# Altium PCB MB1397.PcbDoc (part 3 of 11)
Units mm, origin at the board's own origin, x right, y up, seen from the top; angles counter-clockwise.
Board outline 118.24 x 172.86 mm, 6 copper layers (Top Layer, L2_GND, L3_VCC, L4_SIG, L5_GND, Bottom Layer), stack 1.631 mm thick; 819 components, 632 nets, 2875 pads, 1523 vias.
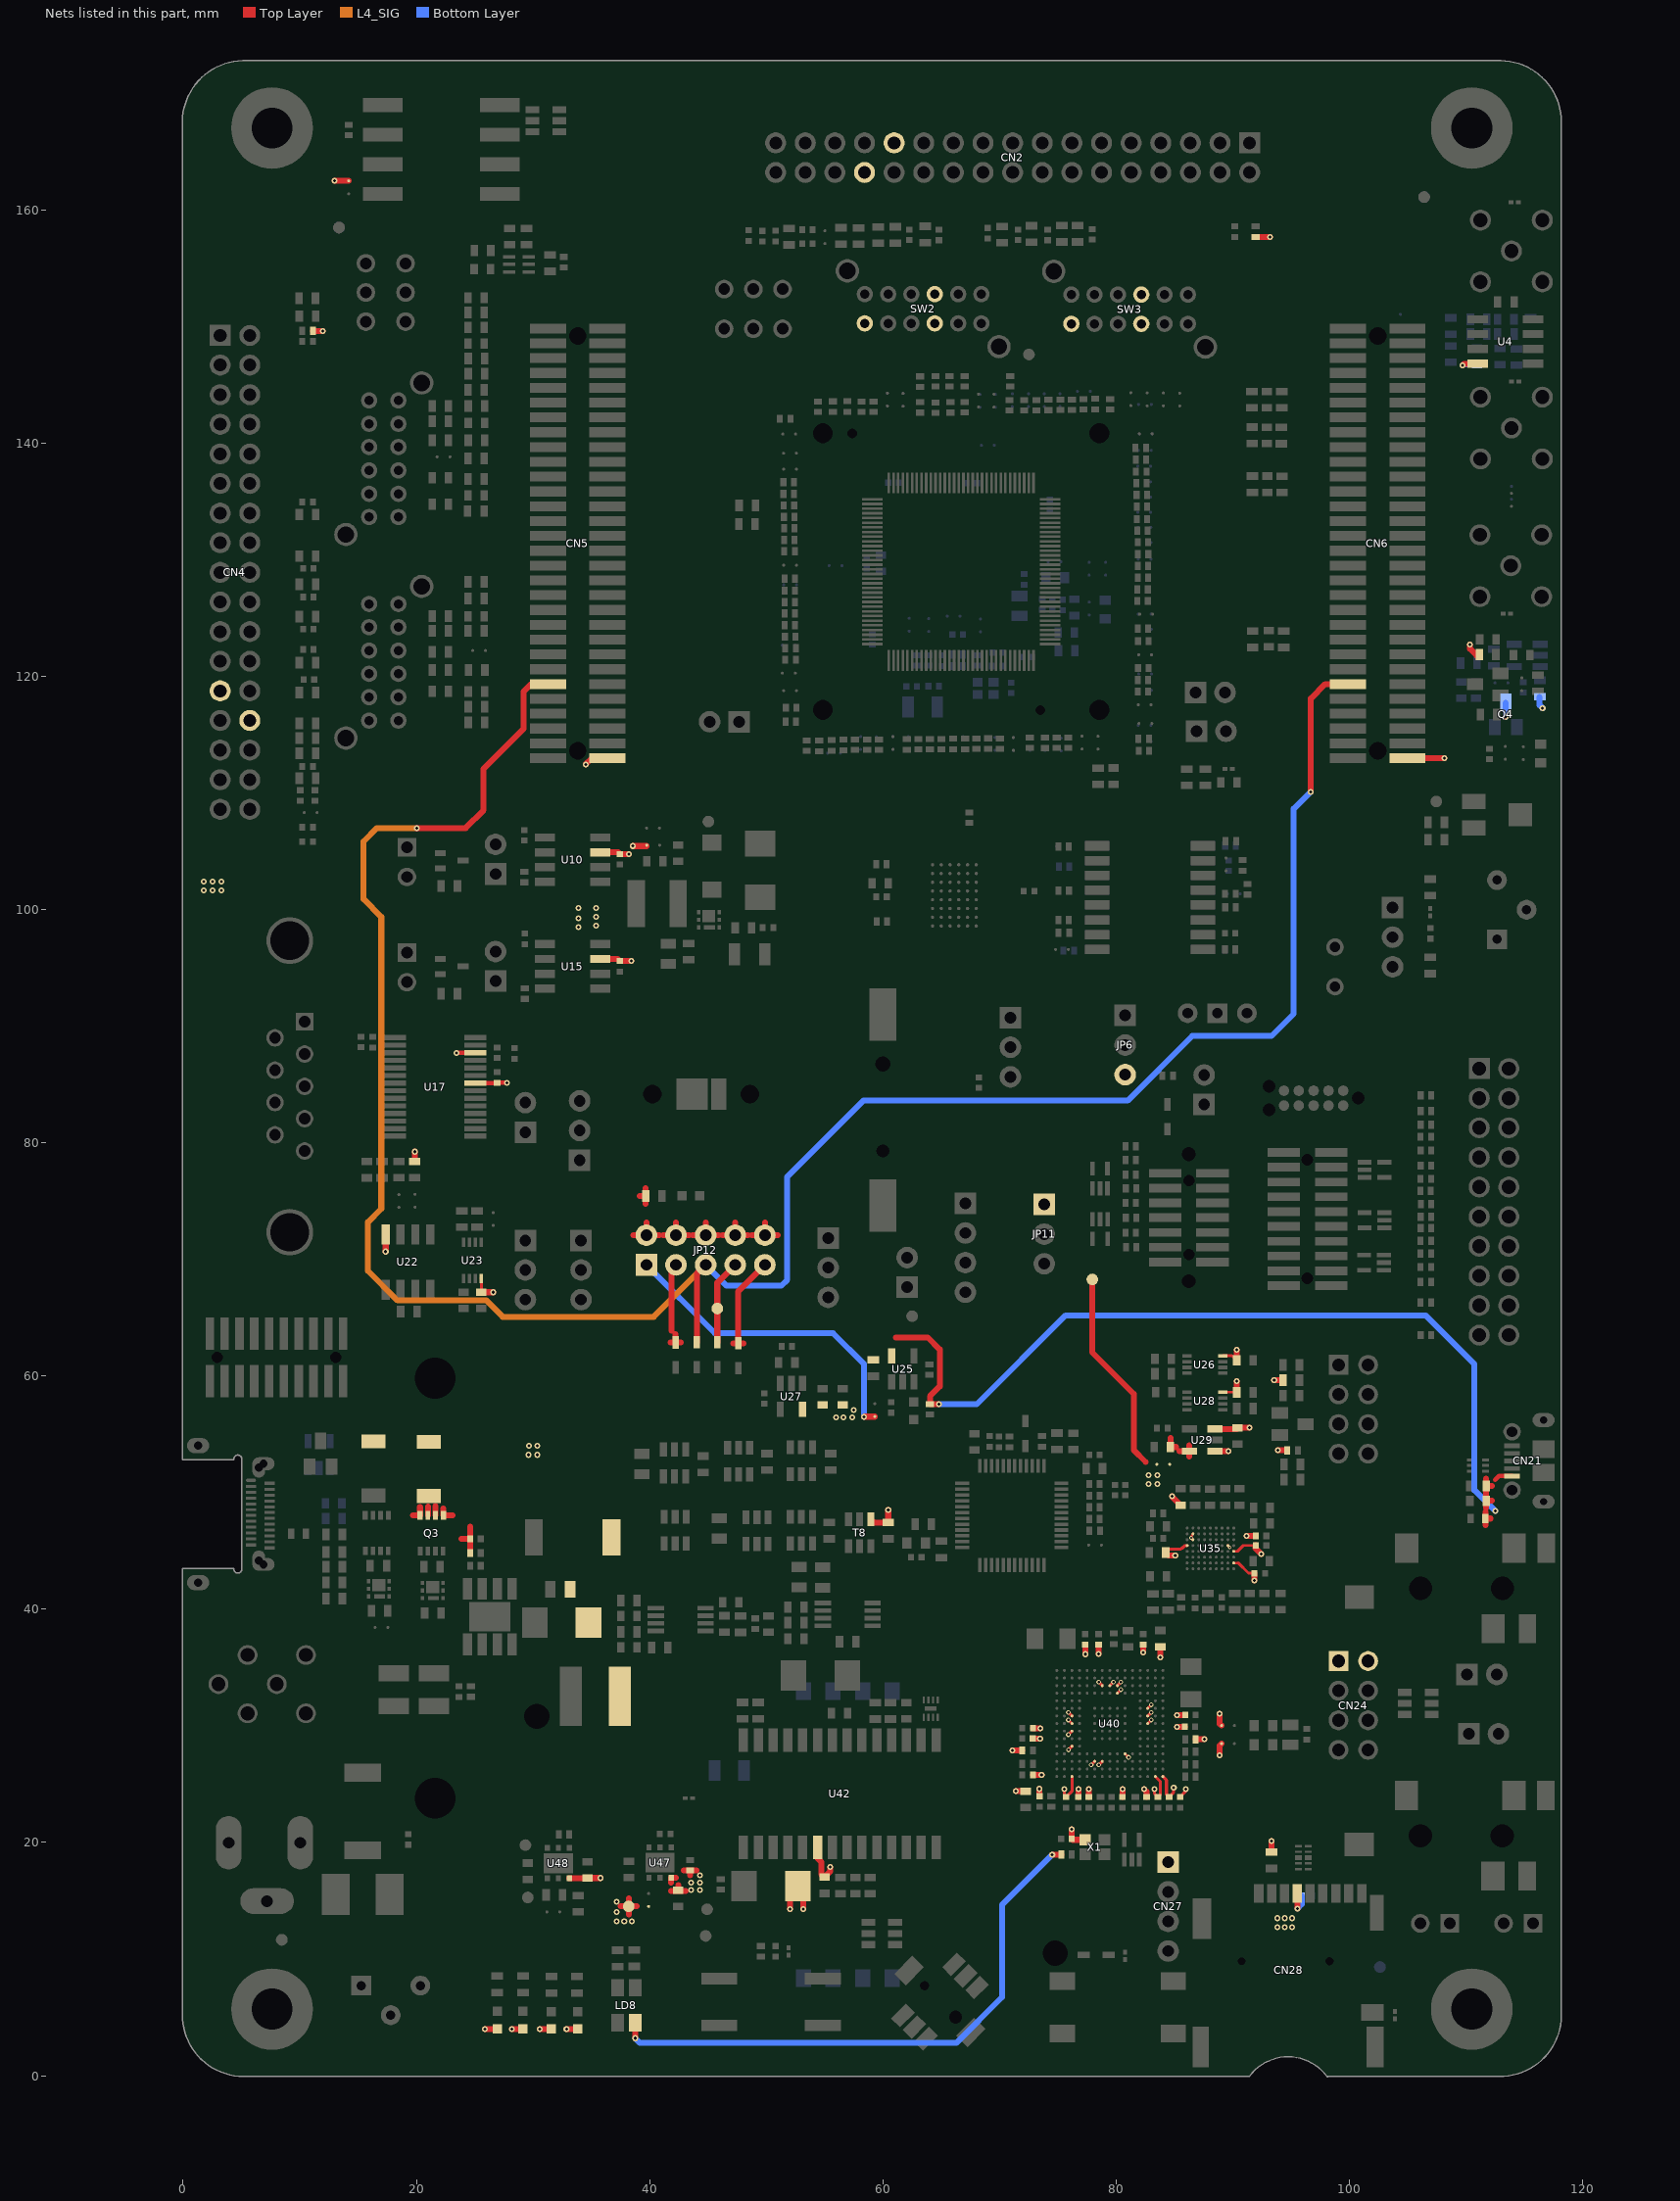
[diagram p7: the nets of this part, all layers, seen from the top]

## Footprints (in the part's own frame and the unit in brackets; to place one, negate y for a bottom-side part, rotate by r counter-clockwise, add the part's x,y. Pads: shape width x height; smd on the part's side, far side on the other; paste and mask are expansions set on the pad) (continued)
ICC_LQFP128_14X14_P040_SOCKET_IRONWOOD_SG-QFE-7011MF [mm]
  rect 1.78x0.225 smd mask+0.038: 1(-7.62,6.2) 2(-7.62,5.8) 3(-7.62,5.4) 4(-7.62,5) 5(-7.62,4.6) 6(-7.62,4.2) 7(-7.62,3.8) 8(-7.62,3.4) 9(-7.62,3) 10(-7.62,2.6) 11(-7.62,2.2) 12(-7.62,1.8) 13(-7.62,1.4) 14(-7.62,1) 15(-7.62,0.6) 16(-7.62,0.2) 17(-7.62,-0.2) 18(-7.62,-0.6) 19(-7.62,-1) 20(-7.62,-1.4) 21(-7.62,-1.8) 22(-7.62,-2.2) 23(-7.62,-2.6) 24(-7.62,-3) 25(-7.62,-3.4) 26(-7.62,-3.8) 27(-7.62,-4.2) 28(-7.62,-4.6) 29(-7.62,-5) 30(-7.62,-5.4) 31(-7.62,-5.8) 32(-7.62,-6.2) 65(7.62,-6.2) 66(7.62,-5.8) 67(7.62,-5.4) 68(7.62,-5) 69(7.62,-4.6) 70(7.62,-4.2) 71(7.62,-3.8) 72(7.62,-3.4) 73(7.62,-3) 74(7.62,-2.6) 75(7.62,-2.2) 76(7.62,-1.8) 77(7.62,-1.4) 78(7.62,-1) 79(7.62,-0.6) 80(7.62,-0.2) 81(7.62,0.2) 82(7.62,0.6) 83(7.62,1) 84(7.62,1.4) 85(7.62,1.8) 86(7.62,2.2) 87(7.62,2.6) 88(7.62,3) 89(7.62,3.4) 90(7.62,3.8) 91(7.62,4.2) 92(7.62,4.6) 93(7.62,5) 94(7.62,5.4) 95(7.62,5.8) 96(7.62,6.2)
  rect 0.225x1.78 smd mask+0.038: 33(-6.2,-7.62) 34(-5.8,-7.62) 35(-5.4,-7.62) 36(-5,-7.62) 37(-4.6,-7.62) 38(-4.2,-7.62) 39(-3.8,-7.62) 40(-3.4,-7.62) 41(-3,-7.62) 42(-2.6,-7.62) 43(-2.2,-7.62) 44(-1.8,-7.62) 45(-1.4,-7.62) 46(-1,-7.62) 47(-0.6,-7.62) 48(-0.2,-7.62) 49(0.2,-7.62) 50(0.6,-7.62) 51(1,-7.62) 52(1.4,-7.62) 53(1.8,-7.62) 54(2.2,-7.62) 55(2.6,-7.62) 56(3,-7.62) 57(3.4,-7.62) 58(3.8,-7.62) 59(4.2,-7.62) 60(4.6,-7.62) 61(5,-7.62) 62(5.4,-7.62) 63(5.8,-7.62) 64(6.2,-7.62) 97(6.2,7.62) 98(5.8,7.62) 99(5.4,7.62) 100(5,7.62) 101(4.6,7.62) 102(4.2,7.62) 103(3.8,7.62) 104(3.4,7.62) 105(3,7.62) 106(2.6,7.62) 107(2.2,7.62) 108(1.8,7.62) 109(1.4,7.62) 110(1,7.62) 111(0.6,7.62) 112(0.2,7.62) 113(-0.2,7.62) 114(-0.6,7.62) 115(-1,7.62) 116(-1.4,7.62) 117(-1.8,7.62) 118(-2.2,7.62) 119(-2.6,7.62) 120(-3,7.62) 121(-3.4,7.62) 122(-3.8,7.62) 123(-4.2,7.62) 124(-4.6,7.62) 125(-5,7.62) 126(-5.4,7.62) 127(-5.8,7.62) 128(-6.2,7.62)
  round 0 hole 1.71 unplated mask+0.05: NPTH1(-11.86,11.86) NPTH2(11.86,11.86) NPTH3(11.86,-11.86) NPTH4(-11.86,-11.86)
  round 0 hole 0.85 unplated mask+0.05: NPTH5(-11.86,-6.78) NPTH6(11.86,9.32)
  Bottom Layer keep-out circle w0.01: c-11.86,11.86 r2.5
  Bottom Layer keep-out circle w0.01: c11.865,11.86 r2.5
  Bottom Layer keep-out circle w0.01: c11.86,-11.86 r2.5
  Bottom Layer keep-out circle w0.01: c-11.86,-11.86 r2.5
  Keep-Out Layer circle w0.01: c11.86,9.32 r0.7
  Keep-Out Layer circle w0.01: c-11.86,11.86 r1.1
  Keep-Out Layer circle w0.01: c11.86,11.86 r1.1
  Keep-Out Layer circle w0.01: c11.86,-11.86 r1.1
  Keep-Out Layer circle w0.01: c-11.86,-11.86 r1.1
  Keep-Out Layer circle w0.01: c-11.86,-6.78 r0.7
  silkscreen extent -13.18,-13.18 13.18,13.18, body extent -14.36,-14.36 14.36,14.36, height 9.86
ICC_MINI-BGA48_9X11_P075 [mm] "IPC"
  round 0.28 smd mask+0.05: A1(-1.875,2.625) A2(-1.125,2.625) A3(-0.375,2.625) A4(0.375,2.625) A5(1.125,2.625) A6(1.875,2.625) B1(-1.875,1.875) B2(-1.125,1.875) B3(-0.375,1.875) B4(0.375,1.875) B5(1.125,1.875) B6(1.875,1.875) C1(-1.875,1.125) C2(-1.125,1.125) C3(-0.375,1.125) C4(0.375,1.125) C5(1.125,1.125) C6(1.875,1.125) D1(-1.875,0.375) D2(-1.125,0.375) D3(-0.375,0.375) D4(0.375,0.375) D5(1.125,0.375) D6(1.875,0.375) E1(-1.875,-0.375) E2(-1.125,-0.375) E3(-0.375,-0.375) E4(0.375,-0.375) E5(1.125,-0.375) E6(1.875,-0.375) F1(-1.875,-1.125) F2(-1.125,-1.125) F3(-0.375,-1.125) F4(0.375,-1.125) F5(1.125,-1.125) F6(1.875,-1.125) G1(-1.875,-1.875) G2(-1.125,-1.875) G3(-0.375,-1.875) G4(0.375,-1.875) G5(1.125,-1.875) G6(1.875,-1.875) H1(-1.875,-2.625) H2(-1.125,-2.625) H3(-0.375,-2.625) H4(0.375,-2.625) H5(1.125,-2.625) H6(1.875,-2.625)
  silkscreen extent -4.7,-5.55 4.55,5.7, body extent -4.55,-5.55 4.55,5.55, height 1.21
ICC_MINISO8_3X3_P065 [mm]
  rect 0.4x1.4 smd mask+0.05: 1(0.975,2.125) 2(0.325,2.125) 3(-0.325,2.125) 4(-0.975,2.125) 5(-0.975,-2.125) 6(-0.325,-2.125) 7(0.325,-2.125) 8(0.975,-2.125)
  silkscreen extent -1.6,-1.55 1.6,1.55, body extent -1.6,-2.58 1.6,2.58, height 1.11
ICC_SO8_5X4_P127 [mm]
  rect 0.7x1.75 smd mask+0.05: 1(-1.905,-2.375) 2(-0.635,-2.375) 3(0.635,-2.375) 4(1.905,-2.375) 5(1.905,2.375) 6(0.635,2.375) 7(-0.635,2.375) 8(-1.905,2.375)
  silkscreen extent -2.58,-2 2.58,2, body extent -2.57,-3 2.57,3, height 1.75
ICC_SO28_18P10X7P60_P127 [mm]
  rect 0.8x2.02 smd mask+0.05: 1(-8.255,-4.59) 2(-6.985,-4.59) 3(-5.715,-4.59) 4(-4.445,-4.59) 5(-3.175,-4.59) 6(-1.905,-4.59) 7(-0.635,-4.59) 8(0.635,-4.59) 9(1.905,-4.59) 10(3.175,-4.59) 11(4.445,-4.59) 12(5.715,-4.59) 13(6.985,-4.59) 14(8.255,-4.59) 15(8.255,4.59) 16(6.985,4.59) 17(5.715,4.59) 18(4.445,4.59) 19(3.175,4.59) 20(1.905,4.59) 21(0.635,4.59) 22(-0.635,4.59) 23(-1.905,4.59) 24(-3.175,4.59) 25(-4.445,4.59) 26(-5.715,4.59) 27(-6.985,4.59) 28(-8.255,4.59)
  silkscreen extent -9.05,-3.8 9.05,3.8, body extent -9.05,-5.16 9.05,5.16, height 2.65
ICC_SOP2-SF_16P_10P3X7P5_P127 [mm]
  rect 0.8x2.1 smd mask+0.05: 1(-4.445,-4.55) 2(-3.175,-4.55) 3(-1.905,-4.55) 4(-0.635,-4.55) 5(0.635,-4.55) 6(1.905,-4.55) 7(3.175,-4.55) 8(4.445,-4.55) 9(4.445,4.55) 10(3.175,4.55) 11(1.905,4.55) 12(0.635,4.55) 13(-0.635,4.55) 14(-1.905,4.55) 15(-3.175,4.55) 16(-4.445,4.55)
  silkscreen extent -5.25,-3.8 5.25,3.8, body extent -5.25,-5.35 5.25,5.35, height 2.66
ICC_SOT23-3L_H1P12 [mm]
  rect 1x1.4 smd mask+0.05: 1(-0.95,-1.1) 2(0.95,-1.1) 3(0,1.1)
  silkscreen extent -1.63,-0.82 1.63,0.82, body extent -1.56,-1.25 1.56,1.25, height 1.12
ICC_SOT23-5L_H1P45 [mm]
  rect 0.6x1.3 smd mask+0.05: 1(-0.95,-1.1) 2(0,-1.1) 3(0.95,-1.1) 4(0.95,1.1) 5(-0.95,1.1)
  silkscreen extent -1.75,-1.68 1.6,0.97, body extent -1.52,-1.25 1.52,1.25, height 1.45
ICC_SSOP28_10P2X5P3_P065 [mm]
  rect 0.45x1.9 smd mask+0.05: 1(-4.225,-3.45) 2(-3.575,-3.45) 3(-2.925,-3.45) 4(-2.275,-3.45) 5(-1.625,-3.45) 6(-0.975,-3.45) 7(-0.325,-3.45) 8(0.325,-3.45) 9(0.975,-3.45) 10(1.625,-3.45) 11(2.275,-3.45) 12(2.925,-3.45) 13(3.575,-3.45) 14(4.225,-3.45) 15(4.225,3.45) 16(3.575,3.45) 17(2.925,3.45) 18(2.275,3.45) 19(1.625,3.45) 20(0.975,3.45) 21(0.325,3.45) 22(-0.325,3.45) 23(-0.975,3.45) 24(-1.625,3.45) 25(-2.275,3.45) 26(-2.925,3.45) 27(-3.575,3.45) 28(-4.225,3.45)
  silkscreen extent -5.25,-2.8 5.25,2.8, body extent -5.25,-3.9 5.25,3.9, height 2
ICC_UDFN6_2X2_P065 [mm] "MCD-01551"
  rect 0.3x1.05 smd mask+0.05: 1(-0.65,-0.85) 2(0,-0.85) 3(0.65,-0.85) 4(0.65,0.85) 5(0,0.85) 6(-0.65,0.85)
  silkscreen extent -1.15,-1.45 1.02,1.02, body extent -1.03,-1.03 1.02,1.02, height 0.56
ICC_UFBGA201_176+25_10X10_P065 [mm] "IPC"
  round 0.25 smd mask+0.05: A1(-4.55,4.55) A2(-3.9,4.55) A3(-3.25,4.55) A4(-2.6,4.55) A5(-1.95,4.55) A6(-1.3,4.55) A7(-0.65,4.55) A8(0,4.55) A9(0.65,4.55) A10(1.3,4.55) A11(1.95,4.55) A12(2.6,4.55) A13(3.25,4.55) A14(3.9,4.55) A15(4.55,4.55) B1(-4.55,3.9) B2(-3.9,3.9) B3(-3.25,3.9) B4(-2.6,3.9) B5(-1.95,3.9) B6(-1.3,3.9) B7(-0.65,3.9) B8(0,3.9) B9(0.65,3.9) B10(1.3,3.9) B11(1.95,3.9) B12(2.6,3.9) B13(3.25,3.9) B14(3.9,3.9) B15(4.55,3.9) C1(-4.55,3.25) C2(-3.9,3.25) C3(-3.25,3.25) C4(-2.6,3.25) C5(-1.95,3.25) C6(-1.3,3.25) C7(-0.65,3.25) C8(0,3.25) C9(0.65,3.25) C10(1.3,3.25) C11(1.95,3.25) C12(2.6,3.25) C13(3.25,3.25) C14(3.9,3.25) C15(4.55,3.25) D1(-4.55,2.6) D2(-3.9,2.6) D3(-3.25,2.6) D4(-2.6,2.6) D5(-1.95,2.6) D6(-1.3,2.6) D7(-0.65,2.6) D8(0,2.6) D9(0.65,2.6) D10(1.3,2.6) D11(1.95,2.6) D12(2.6,2.6) D13(3.25,2.6) D14(3.9,2.6) D15(4.55,2.6) E1(-4.55,1.95) E2(-3.9,1.95) E3(-3.25,1.95) E4(-2.6,1.95) E12(2.6,1.95) E13(3.25,1.95) E14(3.9,1.95) E15(4.55,1.95) F1(-4.55,1.3) F2(-3.9,1.3) F3(-3.25,1.3) F4(-2.6,1.3) F6(-1.3,1.3) F7(-0.65,1.3) F8(0,1.3) F9(0.65,1.3) F10(1.3,1.3) F12(2.6,1.3) F13(3.25,1.3) F14(3.9,1.3) F15(4.55,1.3) G1(-4.55,0.65) G2(-3.9,0.65) G3(-3.25,0.65) G4(-2.6,0.65) G6(-1.3,0.65) G7(-0.65,0.65) G8(0,0.65) G9(0.65,0.65) G10(1.3,0.65) G12(2.6,0.65) G13(3.25,0.65) G14(3.9,0.65) G15(4.55,0.65) H1(-4.55,0) H2(-3.9,0) H3(-3.25,0) H4(-2.6,0) H6(-1.3,0) H7(-0.65,0) H8(0,0) H9(0.65,0) H10(1.3,0) H12(2.6,0) H13(3.25,0) H14(3.9,0) H15(4.55,0) J1(-4.55,-0.65) J2(-3.9,-0.65) J3(-3.25,-0.65) J4(-2.6,-0.65) J6(-1.3,-0.65) J7(-0.65,-0.65) J8(0,-0.65) J9(0.65,-0.65) J10(1.3,-0.65) J12(2.6,-0.65) J13(3.25,-0.65) J14(3.9,-0.65) J15(4.55,-0.65) K1(-4.55,-1.3) K2(-3.9,-1.3) K3(-3.25,-1.3) K4(-2.6,-1.3) K6(-1.3,-1.3) K7(-0.65,-1.3) K8(0,-1.3) K9(0.65,-1.3) K10(1.3,-1.3) K12(2.6,-1.3) K13(3.25,-1.3) K14(3.9,-1.3) K15(4.55,-1.3) L1(-4.55,-1.95) L2(-3.9,-1.95) L3(-3.25,-1.95) L4(-2.6,-1.95) L12(2.6,-1.95) L13(3.25,-1.95) L14(3.9,-1.95) L15(4.55,-1.95) M1(-4.55,-2.6) M2(-3.9,-2.6) M3(-3.25,-2.6) M4(-2.6,-2.6) M5(-1.95,-2.6) M6(-1.3,-2.6) M7(-0.65,-2.6) M8(0,-2.6) M9(0.65,-2.6) M10(1.3,-2.6) M11(1.95,-2.6) M12(2.6,-2.6) M13(3.25,-2.6) M14(3.9,-2.6) M15(4.55,-2.6) N1(-4.55,-3.25) N2(-3.9,-3.25) N3(-3.25,-3.25) N4(-2.6,-3.25) N5(-1.95,-3.25) N6(-1.3,-3.25) N7(-0.65,-3.25) N8(0,-3.25) N9(0.65,-3.25) N10(1.3,-3.25) N11(1.95,-3.25) N12(2.6,-3.25) N13(3.25,-3.25) N14(3.9,-3.25) N15(4.55,-3.25) P1(-4.55,-3.9) P2(-3.9,-3.9) P3(-3.25,-3.9) P4(-2.6,-3.9) P5(-1.95,-3.9) P6(-1.3,-3.9) P7(-0.65,-3.9) P8(0,-3.9) P9(0.65,-3.9) P10(1.3,-3.9) P11(1.95,-3.9) P12(2.6,-3.9) P13(3.25,-3.9) P14(3.9,-3.9) P15(4.55,-3.9) R1(-4.55,-4.55) R2(-3.9,-4.55) R3(-3.25,-4.55) R4(-2.6,-4.55) R5(-1.95,-4.55) R6(-1.3,-4.55) R7(-0.65,-4.55) R8(0,-4.55) R9(0.65,-4.55) R10(1.3,-4.55) R11(1.95,-4.55) R12(2.6,-4.55) R13(3.25,-4.55) R14(3.9,-4.55) R15(4.55,-4.55)
  silkscreen extent -5.22,-5.07 5.07,5.23, body extent -5.07,-5.07 5.07,5.07, height 0.61
ICC_VSSOP8_DCU_R-PDSO-G8_2X2P30_P050 [mm]
  rect 0.3x0.8 smd mask+0.05: 1(-0.75,-1.55) 2(-0.25,-1.55) 3(0.25,-1.55) 4(0.75,-1.55) 5(0.75,1.55) 6(0.25,1.55) 7(-0.25,1.55) 8(-0.75,1.55)
  silkscreen extent -1.05,-1.2 1.05,1.2, body extent -1.05,-1.62 1.05,1.62, height 0.9
ICC_W-CSP-BGA72_4P511X4P023_P050 [mm]
  round 0.25 smd mask+0.05: A1(-2,1.75) A2(-1.5,1.75) A3(-1,1.75) A4(-0.5,1.75) A5(0,1.75) A6(0.5,1.75) A7(1,1.75) A8(1.5,1.75) A9(2,1.75) B1(-2,1.25) B2(-1.5,1.25) B3(-1,1.25) B4(-0.5,1.25) B5(0,1.25) B6(0.5,1.25) B7(1,1.25) B8(1.5,1.25) B9(2,1.25) C1(-2,0.75) C2(-1.5,0.75) C3(-1,0.75) C4(-0.5,0.75) C5(0,0.75) C6(0.5,0.75) C7(1,0.75) C8(1.5,0.75) C9(2,0.75) D1(-2,0.25) D2(-1.5,0.25) D3(-1,0.25) D4(-0.5,0.25) D5(0,0.25) D6(0.5,0.25) D7(1,0.25) D8(1.5,0.25) D9(2,0.25) E1(-2,-0.25) E2(-1.5,-0.25) E3(-1,-0.25) E4(-0.5,-0.25) E5(0,-0.25) E6(0.5,-0.25) E7(1,-0.25) E8(1.5,-0.25) E9(2,-0.25) F1(-2,-0.75) F2(-1.5,-0.75) F3(-1,-0.75) F4(-0.5,-0.75) F5(0,-0.75) F6(0.5,-0.75) F7(1,-0.75) F8(1.5,-0.75) F9(2,-0.75) G1(-2,-1.25) G2(-1.5,-1.25) G3(-1,-1.25) G4(-0.5,-1.25) G5(0,-1.25) G6(0.5,-1.25) G7(1,-1.25) G8(1.5,-1.25) G9(2,-1.25) H1(-2,-1.75) H2(-1.5,-1.75) H3(-1,-1.75) H4(-0.5,-1.75) H5(0,-1.75) H6(0.5,-1.75) H7(1,-1.75) H8(1.5,-1.75) H9(2,-1.75)
  silkscreen extent -2.42,-2.03 2.28,2.17, body extent -2.28,-2.04 2.28,2.04, height 0.78
IND_POWER_CYNTEC_PSI054T [mm]
  rect 1.5x4 smd mask+0.05: 1(-1.8,0) 2(1.8,0)
  silkscreen extent -2.55,-2.55 2.55,2.55, body extent -2.55,-2.55 2.55,2.55, height 4
IND_TDK_VLS6045EX-4R7M [mm]
  rect 1.9x5.1 smd mask+0.05: 1(-2.1,0) 2(2.1,0)
  silkscreen extent -2.75,-3 2.75,3, body extent -3,-3 3,3, height 4.51
L0603 [mm]
  rect 0.8x0.95 smd mask+0.05: 1(-0.8,0) 2(0.8,0)
  silkscreen extent -1.33,-0.6 1.33,0.6, body extent -0.87,-0.47 0.87,0.47, height 0.95
LED_0603_OSRAM_LB-Q39G-L2OO-35-1_BLUE_1A2K_H0P4 [mm]
  rect 0.8x0.8 smd mask+0.05: 1(-0.75,0) 2(0.75,0)
  silkscreen extent -0.85,-0.53 1.28,0.53, body extent -0.85,-0.45 0.85,0.45, height 0.6
LED_0603_OSRAM_LG-Q396-PS-35_GREEN_1A2K_H0P4 [mm]
  rect 0.8x0.8 smd mask+0.05: 1(-0.75,0) 2(0.75,0)
  silkscreen extent -0.85,-0.53 1.28,0.53, body extent -0.85,-0.45 0.85,0.45, height 0.6
LED_0603_OSRAM_LO-Q976-PS-25_ORANGE_1A2K_H0P8 [mm]
  rect 0.8x0.8 smd mask+0.05: 1(-0.75,0) 2(0.75,0)
  silkscreen extent -0.85,-0.53 1.28,0.53, body extent -0.85,-0.45 0.85,0.45, height 0.8
LED_0603_VISHAY_VLMS1300-GS08_RED_1A2K_H0P8 [mm]
  rect 0.8x0.8 smd mask+0.05: 1(-0.75,0) 2(0.75,0)
  silkscreen extent -0.85,-0.53 1.28,0.53, body extent -0.85,-0.45 0.85,0.45, height 0.8
LED_BI-GR_HSMF-A201-A00J1 [mm]
  rect 1.1x1.5 smd mask+0.05: 1(-0.75,-1.5) 2(-0.75,1.5) 3(0.75,1.5) 4(0.75,-1.5)
  silkscreen extent -1.65,-1.85 1.65,1.85, body extent -1.5,-1.85 1.5,1.85, height 2.1
LED_EVERLUCK_CWC12100_WHITE_1A2K [mm] "BOTTOM PLACE"
  rect 1.3x2.7 smd mask+0.05: 1(1.5,0)
  rect 2.7x2.7 smd mask+0.05: 2(-0.8,0)
  silkscreen extent -2.22,-1.63 1.65,1.62, body extent -1.75,-1.5 1.75,1.5, height 2.5
LIGHT_10MM-SQUARE-LIGHT-BAR_LUMEX_LPB-S01110101S-110945 [mm]
  round 0 hole 1.6 slot 3.8 at 90 deg unplated mask+0.05: NPTH1(-4.18,0) NPTH2(4.18,0)
  silkscreen extent -5.08,-5.08 5.08,5.08, body extent -5.08,-5.08 5.08,5.08, height 10.3
LOGO_CE [mm]
  silkscreen extent -1.61,-1.37 1.85,1.07
LOGO_MAIN_1 [mm]
  silkscreen extent -3.36,-2.51 3.52,3.76
LOGO_ROHS [mm]
  silkscreen extent -4.63,-3.03 4.87,2.98
LOGO_ST [mm]
  silkscreen extent -6.18,-2.95 5.25,3.14
MOS_POWERFLAT_2X2_P065 [mm] "MCD-01028  PowerFLAT, 6-Leads, Body 2.1x2.1mm"
  rect 0.35x0.3 smd mask+0.038: 1(-0.65,-0.875) 2(0,-0.875)
  rect 0.35x0.3 smd mask+0.05: 3(0.65,-0.875) 4(0.65,0.875) 5(0,0.875) 6(-0.65,0.875)
  rect 0.35x0.95 smd mask+0.05: 7(0.65,0.05)
  rect 1.05x1.125 smd mask+0.038: 8(-0.3,-0.012)
  silkscreen extent -1.2,-1.2 1.05,1.05, body extent -1.05,-1.05 1.05,1.05, height 0.81
MOS_POWERFLAT_3P3X3P3_P065 [mm]
  rect 0.4x0.75 smd mask+0.05: 1(-0.975,-1.525) 2(-0.325,-1.525) 3(0.325,-1.525) 4(0.975,-1.525) 6(0.325,1.525) 7(-0.325,1.525)
  rect 0.45x0.75 smd mask+0.05: 5(1,1.525) 8(-1,1.525)
  Top Layer region: -1.755,0.2 -1.755,-0.2 -1.225,-0.2 -1.225,-0.5 1.225,-0.5 1.225,-0.2 1.755,-0.2 1.755,0.2 1.225,0.2 1.225,1.9 -1.225,1.9 -1.225,0.2
  silkscreen extent -1.63,-1.55 1.63,1.55, body extent -1.75,-1.75 1.75,1.75, height 0.91
MOS_SOT23 [mm]
  rect 1x1.4 smd mask+0.05: 1(-0.95,-1.1) 2(0.95,-1.1) 3(0,1.1)
  silkscreen extent -1.63,-0.82 1.63,0.82, body extent -1.56,-1.25 1.56,1.25, height 1.1
MOS_SOT23-5L [mm]
  rect 0.6x1.3 smd mask+0.05: 1(-0.95,-1.1) 2(0,-1.1) 3(0.95,-1.1) 4(0.95,1.1) 5(-0.95,1.1)
  silkscreen extent -1.6,-0.95 1.6,0.97, body extent -1.52,-1.25 1.52,1.25, height 1.45
MOS_SOT23-6L [mm]
  rect 0.6x1.2 smd mask+0.05: 1(-0.95,-1.15) 2(0,-1.15) 3(0.95,-1.15) 4(0.95,1.15) 5(0,1.15) 6(-0.95,1.15)
  silkscreen extent -1.53,-0.87 1.53,0.87, body extent -1.52,-1.5 1.52,1.5, height 1.3
NPN_SOT23 [mm]
  rect 1x1.4 smd mask+0.05: 1(-0.95,-1.1) 2(0.95,-1.1) 3(0,1.1)
  silkscreen extent -1.63,-0.82 1.63,0.82, body extent -1.56,-1.25 1.56,1.25, height 1.1
NPTH_350 [mm]
  round 0 hole 3.5 unplated mask+0.05: 1(0,0)
  silkscreen extent -2,-2 2,2
OSC_NDK_NZ2520SB_4P [mm]
  rect 1x1 smd mask+0.05: 1(-0.825,-0.625) 2(0.825,-0.625) 3(0.825,0.625) 4(-0.825,0.625)
  silkscreen extent -1.43,-1.22 1.2,1.05, body extent -1,-0.77 -0.6,-0.38, height 0.91
PHO_SENBAN_GL55XX [mm]
  round 1.5 hole 0.9 mask+0.05: 1(-1.7,0) 2(1.7,0)
  silkscreen extent -2.6,-2.25 2.6,2.25, body extent -2.58,-1.3 2.58,1.3, height 5.21
POT_BOURNS_3314J-1 [mm]
  rect 1.3x2 smd mask+0.05: 1(1.15,-2) 3(-1.15,-2)
  rect 2x2 smd mask+0.05: 2(0,2)
  silkscreen extent -2.5,-3 2.5,2.25, body extent -2.5,-2.5 2.5,2.5, height 2.73
POT_BOURNS_3386P [mm]
  rect 1.7x1.7 hole 0.8 mask+0.05: 1(-2.54,0.02)
  round 1.7 hole 0.8 mask+0.05: 2(0,-2.52) 3(2.54,0.02)
  silkscreen extent -4.8,-4.8 4.8,4.8, body extent -4.8,-4.8 4.8,4.81, height 4.96
PTC_BEL-FUSE_1812_0ZCG0260FF2C [mm]
  rect 2.4x3.5 smd mask+0.05: 1(-2.3,0) 2(2.3,0)
  silkscreen extent -1,-1.73 1,1.73, body extent -2.36,-1.71 2.36,1.71, height 1.2
PTH_350_700 [mm]
  round 7 hole 3.5 mask+0.05: 1(0,0)
  silkscreen extent -3.75,-3.75 3.75,3.75
R0402 [mm]
  rect 0.51x0.7 smd mask+0.05: 1(-0.45,0) 2(0.45,0)
  silkscreen extent -0.72,-0.43 0.72,0.43, body extent -0.52,-0.3 0.52,0.3, height 0.4
R0603 [mm]
  rect 0.64x1 smd mask+0.05: 1(-0.7,0) 2(0.7,0)
  silkscreen extent -1.05,-0.58 1.05,0.58, body extent -0.9,-0.5 0.9,0.5, height 0.56
R0805 [mm]
  rect 0.85x1.3 smd mask+0.05: 1(-0.875,0) 2(0.875,0)
  silkscreen extent -0.33,-0.67 0.33,0.67, body extent -1.05,-0.68 1.05,0.68, height 0.65
R1206_H0P55 [mm]
  rect 1x1.9 smd mask+0.05: 1(-1.3,0) 2(1.3,0)
  silkscreen extent -0.67,-0.85 0.67,0.85, body extent -1.6,-0.85 1.6,0.85, height 0.65
REG_SOT23-5L [mm]
  rect 0.6x1.3 smd mask+0.05: 1(-0.95,-1.1) 2(0,-1.1) 3(0.95,-1.1) 4(0.95,1.1) 5(-0.95,1.1)
  silkscreen extent -1.6,-0.95 1.6,0.97, body extent -1.52,-1.25 1.52,1.25, height 1.1
SOLDER-BRIDGE_R0603-0R [mil]
  round 10 smd paste-393.7 mask+4: 1(-19.68,0) 2(23.62,0)
  Top Layer region: -5.91,19.68 13.78,0 -5.91,-19.69 47.24,-19.69 47.24,19.68 -5.91,19.68
  Top Layer region: -47.24,-19.69 -47.24,19.68 -15.75,19.68 3.94,0 -15.75,-19.69 -47.24,-19.69
  silkscreen extent -50,-23 50,23, body extent -36,-20 36,20, height 22
STICKER_25X9 [mm] "Sticker 25mm x 9mm"
  silkscreen extent -12.5,-4.5 12.5,4.5
SWI_C&K_KSC721GLFS_BLUE [mm] "BLUE"
  rect 3.1x1 smd mask+0.05: 1(-4.45,2) 2(4.45,2) 3(-4.45,-2) 4(4.45,-2)
  silkscreen extent -3.25,-3.25 3.25,3.25, body extent -5,-3.25 5,3.25, height 2.9
SWI_DHS-ELECTRONICS_MS-22D16_2P2T [mm]
  round 1.6 hole 1 mask+0.05: 1(-2.5,-1.7) 2(0,-1.7) 3(2.5,-1.7) 4(-2.5,1.7) 5(0,1.7) 6(2.5,1.7)
  silkscreen extent -4.55,-2.5 4.55,1.8, body extent -4.55,-1.9 4.55,1.9, height 7.5
SWI_DHS-ELECTRONICS_SS42D02_4P2T [mm]
  round 1.4 hole 0.8 mask+0.05: 1(-5,-1.25) 2(-3,-1.25) 3(-1,-1.25) 4(1,-1.25) 5(3,-1.25) 6(5,-1.25) 7(1,1.25) 8(3,1.25) 9(5,1.25) 10(-5,1.25) 11(-3,1.25) 12(-1,1.25)
  round 2 hole 1.4 mask+0.05: PTH1(-6.5,3.25) PTH2(6.5,-3.25)
  silkscreen extent -7.35,-4.3 7.35,3.45, body extent -7.35,-3.45 7.35,3.45, height 11.8
SWI_EAO_09-03290-01_EXTENDED_STRAIGHT_BLACK [mm]
  rect 1.7x1.7 hole 0.9 mask+0.05: 1(0,0)
  round 1.7 hole 0.9 mask+0.05: 2(0,-2.54) 3(0,2.54)
  silkscreen extent -1.25,-5 1.25,5, body extent -1.25,-5 1.25,5, height 7.9
SWI_WEALTHMETAL_TD-0341_4P_BLACK [mm]
  rect 1.52x2.16 smd mask+0.05: 1(-2.25,-4.75) 2(-2.25,4.75) 3(2.25,-4.75) 4(2.25,4.75)
  silkscreen extent -3,-3.5 3,3.5, body extent -3,-5.15 3,5.15, height 7.55
SWI_XIEJIA_MT-008A_6P [mm]
  rect 1.8x1.1 smd mask+0.05: 1(-3.1,1.4) 2(-3.1,0) 3(-3.1,-1.4) 4(3.1,1.4) 5(3.1,0) 6(3.1,-1.4)
  rect 2.2x1.4 smd mask+0.05: 7(0,3.75) 8(0,-3.75)
  round 0 hole 0.8 unplated paste-10 mask+0.05: NPTH1(0,1.9)
  round 0 hole 1.1 unplated paste-10 mask+0.05: NPTH2(0,-1.9)
  silkscreen extent -3.7,-3.7 3.7,3.7, body extent -3.85,-3.75 3.85,3.75, height 5.2
TP_SMD_1MM [mm]
  round 1 smd paste-10 mask+0.05: 1(0,0)
  silkscreen extent -0.7,-0.7 0.7,0.7

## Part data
B1: library part MCD-00132, "Joystick, 4 dir, 1 OK"
B2: library part MCD-00176, "Switch HW BLUE High4.3mm 2.25 Newtons"
B3: library part MCD-00001, "Non-Open Push-Button 0.1A 24V BLACK"
C1 C16 C49: library part MCD-00198, "Capacitor, MLCC, 1nF, 16V, X7R, 10%, 0402, T=0.5mm"
C2 C3 C4 C5 C6 C7 C8 C9 C10 C11 C22 C23 C24 C26 C29 C31 C33 C34 C37 C39 C40 C42 C44 C47 C48 C50 C51 C52 C53 C54 C55 C56 C57 C58 C59 C63 C72 C77 C78 C80 C82 C83 C93 C94 C96 C98 C100 C106 C107 C116 C117 C118 C125 C128 C130 C131 C132 C133 C134 C136 C137 C138 C139 C140 C141 C142 C143 C144 C145 C146 C147 C148 C157 C160 C161 C162 C164 C165 C168 C169 C170 C173 C174 C175 C176 C184 C186: library part MCD-00006, "Capacitor, MLCC, 100nF, 16V, X7R, 10%, 0402, T=0.5mm"
C12 C38 C71 C74: library part MCD-00011, "Capacitor, MLCC, 10nF, 16V, X7R, 10%, 0402, T=0.5mm"
C13 C28 C36 C45 C60 C61 C62 C64 C65 C67 C69 C70 C108 C110 C111 C119 C120 C126 C127 C153 C154 C155 C158 C159 C179: library part MCD-00211, "Capacitor, MLCC, 100nF, 16V, X7R, 10%, 0603, T=0,8mm"
C14 C15 C17 C18 C19 C20 C21 C25 C27 C32: library part MCD-01188, "Capacitor,120pF,50V,NPO,5%,0603"
C30 C180: library part MCD-01124, "Capacitor, MLCC, 10¦ÌF, 10V, X5R, 10%, 0603, T=0.8mm"
C35 C81 C171: library part MCD-01101, "Capacitor,100pF,50V,X7R,10%,0603"
C41 C121 C152: library part MCD-00559, "Capacitor, Tantalum, 47uF, 16V, 10%, TypeC"
C43 C66 C68 C73 C76 C79 C85 C87 C92 C99 C101 C112 C135 C167: library part MCD-00010, "Capacitor, MLCC, 1uF, 16V, X5R, 10%, 0603, T=0,8mm"
C46 C75 C84 C86 C88 C89 C90 C91 C97 C113 C149 C150 C151 C156 C163: library part MCD-00009, "Capacitor, MLCC, 4.7uF, 16V, X5R, 10%, 0603, T=0.8mm"
C95: library part MCD-00203, "Capacitor, MLCC, 22pF, 50V, C0G, 5%, 0402, T=0,5mm"
C102: library part MCD-00101, "Capacitor, MLCC, 22uF, 6V3, X5R, 20%, 0805, T=1,25mm"
C103 C104 C105 C114: library part MCD-00012, "Capacitor, MLCC, 2.2uF, 10V, X5R, 10%, 0603, T=0,8mm"
C109: library part MCD-00142, "Capacitor, Tantalum, 220uF, 10V, 10%, TypeC"
C115 C122: library part MCD-00008, "Capacitor, MLCC, 2.2uF, 16V, X7R, 10%, 1206, T=1,15mm"
C123 C124: library part MCD-01056, "Capacitor, X7R, 10¦ÌF, 50V, 20%, 1210, T=2.5mm"
C129 C166: library part MCD-00014, "Capacitor, MLCC, 10uF, 25V, X5R, 10%, 0805, T=0,85mm"
C172: library part MCD-00016, "Capacitor, MLCC, 20pF, 50V, NPO, 5%, 0402, T=0,5mm"
C177 C178: library part MCD-00556, "Capacitor, MLCC, 3.9pF, 50V, NPO, +-0.25pF, 0402, T=0,5mm"
C181: library part MCD-00205, "Capacitor, MLCC, 100pF, 50V, NPO, 5%, 0402, T=0,5mm"
C182 C183: library part MCD-01374, "Capacitor, MLCC, 5.6pF, 50V, NPO, 5%, 0402, T=0,5mm"
C185: library part MCD-00637, "Capacitor, MLCC, 10pF, 50V, NPO, 5%, 0603, T=0,8mm"
CN1: library part MCD-00131, "Socket, 4x2, 2.54mm, RA, SMT, Height 5.72mm"
CN2 CN4: library part MCD-00583, "Header, 17x2, 2.54mm, VR, TH, Height 8.89mm/2.92mm, shrouded"
CN3 CN7 CN8: library part MCD-01181, "SMB type right angle jack for PCB"
CN5 CN6: library part MCD-00576, "Header 30x2, 1.27mm, VR, CMS, Height 7.24mm"
CN9 CN32 JP1 JP2 JP4 JP8 JP10 JP16 JP17 JP18: library part MCD-00045, "Header, 2x1, 2,54mm, VR, TH, Height 5.84mm/2.54mm"
CN10 CN12 CN29 CN30: library part MCD-00314, "Header, 2x1, 2.54mm, VR, TH, Height 6mm/3mm"
CN11: library part MCD-00127, "Header, DB9, RA, TH, Height 13.57mm"
CN13: library part MCD-00558, "Battery Coin Cell holder, CR1220_12mm, Height 4.25mm"
CN14: library part MCD-01058, "Header, 2.54mm, 10x2, VR, TH, Height 9.1mm/3,1mm"
CN15: library part MCD-00031, "Tag_Connector Header, 10x2, No legs"
CN16: library part MCD-01226, "Header 5x2, 1.27mm, Dual row, Straight, Surface mount, vertical male connector. 3.05mm lead. Mates with FFSD connector. Footprint compatible with FTSH-107-01-L-DV,-K,-A,-P,-ES (STDC14 MEDIUM)"
CN17 CN19: library part MCD-01561, "Header 10x2, 1.27mm, VR, CMS, Height 3.05mm with alignment pin"
CN18 CN27: library part MCD-00029, "Header, 4x1, 2,54mm, VR, TH, Height 5.84mm/2.54mm"
CN20: library part MCD-01174, "Socket, 4x2, 2.54mm, VR, TH, Height 6.8mm, Double row"
CN21: library part MCD-00028, "USB-MICRO-B, 0.65mm, RA, SMT, Bottom Mount,"
CN22: library part MCD-00678, "USB Type C certified Connector SMT Mid-mount"
CN23: library part MCD-00682, "Connector Jack socket Stereo 3.5mm, 3 pins, RA, SMT, Blue (Line input)"
CN24: library part MCD-01195, "socket, 4x2, 2.54mm, VR, TH, Height 6.8mm, Double row"
CN25: library part MCD-00173, "DC-Power-Jack, 2.5mm, 5A, RA, TH"
CN26: library part MCD-00018, "Connector Jack socket Stereo 3.5mm, 3 pins, RA, SMT, Green (Line output)"
CN28: library part MCD-00023, "MicroSD Card Conn, Reversed-Type, Mnt Push-Push, Positionning holes"
CN31: "IC Card Socket 8 pin, SMT Open for Smartcard"
D1: library part MCD-00606, "Low Drop power Schottky rectifier(1A, 40V, 0.37 V)"
D2 D3 D4 D5 D6 D7 D11: library part MCD-00034
D8 D9: library part MCD-01087, "Low drop power Schottky rectifier(2A, 40V, 0.34V)"
D10: library part MCD-01229, "3 line IPAD, EMI filter for SIM card applications"
F1: library part MCD-00624, "SMD, PTC resettable fuse, IH:2.6A, IT:5A, Vdc_max:8V, Rmax:47mohm, BELFUSE"
H1 H2 H5 H6: library part MCD-00328
H3 H4: library part MCD-01368
HW2: library part MCD-00625, "STMicroelectronics logo footprint for PCB"
HW3: library part MCD-00628, "ROHS logo footprint for PCB"
HW4: library part MCD-00627, "Hand ESD logo footprint for PCB"
HW5: library part MCD-00626, "CE logo footprint for PCB"
JP5 JP6 JP7 JP9 JP11 JP13 JP14 JP15: library part MCD-00111, "Header, 3x1, 2,54mm, VR, TH, Height 5.84mm/2.54mm"
JP12: library part MCD-01203, "Header, 5x2, 2,54mm, VR, TH, Height 5.84mm/2.54mm - Shunt Fitted 1-2"
L1 L3 L6 L7 L8 L9: library part MCD-00047, "SMD Chip ferrite bead, 600R@100MHz +/-25%, 350mA, 500mohm DC, 0603, T=0.8mm"
L2: library part MCD-01190, "SMD power inductor. 82uH, 1.0A, 400mohm, 4.9x4.9x4.0mm"
L4: library part MCD-00150, "Through HOLE DC power EMI line filter, 40dB min (1MHz - 1GHz) insertion loss"
L5: library part MCD-01239, "FIXED IND 4.7UH 4.2A 35 MOHM SMD"
LD1 LD6: library part MCD-00588, "LED Green, 0603 SMD, Forward Voltage Typ=2V, Max=2.5V"
LD2: library part MCD-00590, "LED Orange, 0603 SMD, Forward Voltage Min=1.6V, Max=2.4V"
LD3 LD7: library part MCD-00587, "LED Red, 0603 SMD, 2V Forward Voltage"
LD4: library part MCD-00585, "LED Blue, 0603 SMD, Forward Voltage Min=2,8V, Max=3,8V"
LD5: library part MCD-01186, "White SMD LED lamp, Forward Voltage Typ=2.8V, Max=3.6V"
LD8: library part MCD-00051, "LED Bicolor"
LPB1: library part MCD-01191, "10mm Square Light Bar."
Q1: library part MCD-00151, "N-channel enhancement mode field-effect transistor"
Q2 Q3: library part MCD-01126, "Power Mosfet, P-channel,VDS -30V,RDS 12mohm typ,ID -9A"
Q4: library part MCD-00073, "NPN Bipolar Transistor"
R1 R26 R27 R28 R29 R30 R34 R35 R36 R37 R38 R39 R40 R41 R42 R43 R44 R45 R46 R47 R48 R49 R50 R53 R54 R60 R62 R63 R68 R69 R70 R71 R74 R75 R78 R79 R81 R82 R83 R84 R85 R87 R88 R89 R90 R93 R94 R96 R97 R98 R101 R102 R107 R108 R109 R112 R116 R118 R121 R123 R127 R130 R131 R132 R133 R134 R135 R136 R137 R138 R139 R140 R141 R142 R143 R144 R145 R146 R147 R148 R149 R150 R207 R210 R239 R243 R313 R314 R315 R317: library part MCD-00052, "Resistor,0R,0402,5%,1/16W"
R2 R3 R4 R5 R6 R7 R8 R10 R11 R12 R13 R15 R17 R18 R21 R31 R52 R55 R58 R61 R64 R72 R77 R86 R91 R92 R99 R100 R103 R110 R113 R114 R119 R120 R125 R126 R128 R151 R153 R154 R155 R216 R223 R232 R240 R245 R257 R258 R267: library part MCD-00056, "Resistor,0R,0603,5%,1/10W"
R9 R23: library part MCD-00184, "Resistor,3K3,0402,1%,1/16W"
R14: library part MCD-00520, "Resistor,7K5,0603,1%,1/10W"
R16 R226 R237 R279 R281 R282 R291: library part MCD-00065, "Resistor,4K7,0402,1%,1/16W"
R19: library part MCD-00486, "Resistor,51R,0603,1%,1/10W"
R20 R25 R51 R66 R95 R122: library part MCD-00540, "Resistor,9K1,0603,1%,1/10W"
R22 R24 R59 R76 R104 R115: library part MCD-00382, "Resistor,1K3,0603,1%,1/10W"
R32 R56 R65 R106: library part MCD-00364, "Resistor,1K1,0603,1%,1/10W"
R33 R57 R67 R105: library part MCD-00352, "Resistor,3K3,0603,1%,1/10W"
R73 R80: library part MCD-00217, "Resistor,1K5,0603,1%,1/10W"
R111 R220 R231 R297 R300: library part MCD-00442, "Resistor,270R,0603,1%,1/10W"
R117 R176 R213 R219 R264 R273 R274 R275 R276 R316: library part MCD-00220, "Resistor,10K,0603,1%,1/10W"
R124 R311: library part MCD-00222, "Resistor,47K,0603,1%,1/10W"
R129 R159 R160 R167 R168 R169 R170 R173 R178 R319 R320 R321 R322: library part MCD-00455, "Resistor,33R,0402,1%,1/16W"
R152 R172 R310: library part MCD-00456, "Resistor,33R,0603,1%,1/10W"
R156 R162: library part MCD-00164, "Resistor,220K,0402,1%,1/16W"
R157 R158 R164 R246 R250 R254 R259 R301 R302 R303 R304 R305 R306 R307 R308: library part MCD-00070, "Resistor,1K,0603,1%,1/10W"
R161 R163 R166 R171 R180 R182 R183 R184 R186 R195 R197 R200 R203 R212 R214 R217 R225 R234 R235 R261 R272 R278 R280 R283 R286 R288 R289 R294: library part MCD-00053, "Resistor,10K,0402,1%,1/16W"
R165 R181 R192: library part MCD-00338, "Resistor,120R,0603,1%,1/10W"
R174: library part MCD-01158, "GL55 series? photoconductive cell: Light resistance 10Lux range 10-20KOhm, Dark 1MOhm"
R175: library part MCD-01111, "Resistor,10R,0805,1%,Stackpole,1/4W"
R177: library part MCD-01185, "Resistor, 1R, 1206, 1%, 1/4W"
R179: library part MCD-00530, "Resistor,8K2,0603,1%,1/10W"
R185 R188 R189 R193 R205 R209 R211: library part MCD-00189, "Resistor,22R,0402,1%,1/16W"
R187 R266 R284 R285 R312: library part MCD-00119, "Resistor,100R,0402,1%,1/16W"
R190 R191: library part MCD-00430, "Resistor,22K,0603,1%,1/10W"
R194 R196 R199 R204 R206 R208: library part MCD-00481, "Resistor,47R,0402,1%,1/16W"
R198: library part MCD-00500, "Resistor,620R,0603,1%,1/10W"
R201 R202 R215 R218 R222 R228 R229 R230 R233 R241 R242 R287 R290: library part MCD-00223, "Resistor,100K,0603,1%,1/10W"
R221 R309: library part MCD-00527, "Resistor,820R,0402,1%,1/16W"
R224: library part MCD-00063, "Resistor,47K,0402,1%,1/16W"
R227: library part MCD-00323, "Resistor, 1R, 0805, 1%, 1/8W"
R236: library part MCD-00064, "Resistor,510R,0402,1%,1/16W"
R238: library part MCD-01152, "Resistor,24R,0805,1%,1/8W"
R244: library part MCD-00458, "Resistor,330K,0603,1%,1/10W"
R247: library part MCD-00531, "Resistor,82K,0402,1%,1/16W"
R248: library part MCD-01189, "Resistor,21K,0603,1%,1/10W"
R249: library part MCD-00224, "Resistor,100R,0603,1%,1/10W"
R251: library part MCD-00285, "Resistor,15K,0402,5%,1/16W"
R252: library part MCD-01153, "Resistor,620R,0805,1%,1/8W"
R253: library part MCD-01154, "Resistor,10K,0805,1%,1/8W"
R255 R256: library part MCD-00345, "Resistor,20R,0603,1%,1/10W"
R260 R265: library part MCD-00454, "Resistor,300K,0603,1%,1/10W"
R262 R270: library part MCD-01151, "Resistor,6K04,0603,1%,1/10W"
R263 R323: library part MCD-01171, "Resistor,49K9,0603,1%"
R268: library part MCD-01150, "Resistor,357K,0603,1%,1/10W"
R269: library part MCD-00185, "Resistor,3K,0402,1%,1/16W"
R271: library part MCD-00366, "Resistor,11K,0603,1%,1/10W"
R277: library part MCD-00055, "Resistor,2K7,0402,1%,1/16W"
R292: library part MCD-00422, "Resistor,20K,0603,1%,1/10W"
R293: library part MCD-01155, "Resistor,10K2,0603,1%,1/10W"
R295 R296: library part MCD-00197, "Resistor,330R,0603,1%,1/10W"
R298: library part MCD-00462, "Resistor,360R,0603,1%,1/10W"
R299: library part MCD-00354, "Resistor,470R,0603,1%,1/10W"
R318: library part MCD-00342, "Resistor,180R,0603,1%,1/10W"
RV1: library part MCD-01169, "4mm Square Trimming Potentiometer 10K OHM 0.25W PC PIN"
RV2: library part MCD-00575, "TRIMMER 10K OHM 0.5W PC PIN"
RV3: library part MCD-01156, "TRIMMER 50K OHM 0.5W PC PIN"
SB1 SB3 SB4 SB5 SB6 SB7 SB8 SB9 SB11 SB12 SB13 SB15 SB16 SB18 SB20 SB21 SB23 SB24 SB25 SB26 SB27 SB28 SB29 SB31 SB33 SB34 SB35 SB40 SB41 SB42 SB43 SB44 SB46 SB47 SB48 SB75 SB84 SB96 SB107 SB110 SB111 SB119 SB121 SB122 SB123: library part MCD-00071, "Solder Bridge ON"
SB2 SB10 SB14 SB17 SB19 SB22 SB30 SB32 SB36 SB37 SB38 SB39 SB45 SB49 SB50 SB51 SB52 SB53 SB54 SB55 SB56 SB57 SB58 SB59 SB60 SB61 SB62 SB63 SB64 SB65 SB66 SB67 SB68 SB69 SB70 SB71 SB72 SB73 SB74 SB76 SB77 SB78 SB79 SB80 SB81 SB82 SB83 SB85 SB86 SB87 SB88 SB89 SB90 SB91 SB92 SB93 SB94 SB95 SB97 SB98 SB99 SB100 SB101 SB102 SB103 SB104 SB105 SB106 SB108 SB109 SB112 SB113 SB114 SB115 SB116 SB117 SB118 SB120: library part MCD-00072, "Solder Bridge OFF"
SW1 SW4: library part MCD-01180, "vertical slider switch 2x(A to 2B)"
SW2 SW3 SW5 SW6: library part MCD-01179, "Vertical slide switch 4x (A to 2B)"
SW7: library part MCD-00566, "Mechanical Slide Switches 1K2 BLK ACT GOLD STRT MNT"
T1 T9 T10: library part MCD-01028, "N-channel 20 V, 0.025 O typ., 6 A STripFET? V Power MOSFET in a PowerFLAT? 2x2 package"
T2 T3 T4 T5 T6 T7 T8: library part MCD-00573, "[Obsolete] Power MOSFET - P-channel 20 V, 0.0195 OHM typ., 7 A STripFET H7 -  SOT23-6L"
TP1 TP2 TP3 TP4 TP5 TP6 TP7 TP8 TP9 TP10 TP11: library part MCD-00074, "Test Point 1mm"
U1 U55: library part MCD-00163, "Very low capacitance ESD protection"
U2 U5 U7: library part MCD-01242, "Single-line low capacitance Transil for bidirectional ESD protection 6V1"
U3: library part MCD-01551, "IC, 2.25 V low-voltage local digital temperature sensor, UDFN-6L"
U4: library part MCD-01205, "Wide-band Rail-to-Rail operational amplifiers with standby function"
U6: "ARM? Cortex?-M4 32-bit MCU, 512 KB Flash, 96 KB RAM, 5x USART, timers, ADC, DAC, comm. I/F, 1.65-3.6V, with footprint for socket IRONWOOD SG-QFE-7011MF"
U8: library part MCD-01204, "1.24V adjustable shunt voltage reference, Precision 0.5%"
U9 U14 U44 U50 U51 U52: library part MCD-00170, "ESD protection 6V1"
U10 U15: library part MCD-00129, "High-Speed CAN Flexible Data Rate Transceiver"
U11: library part MCD-01071, "SRAM,?8Mb,?10ns, 512Kx16bits, Async,?3.3v"
U12 U54: library part MCD-01128, "Micron Serial NOR Flash Memory"
U13 U16: library part MCD-01228, "Automotive dual-line Transil, transient voltage suppressor (TVS) for CAN bus. Compliant with interfaces in automotive: CAN-FD, LIN, FlexRay, MOST, SENT, USB"
U17: library part MCD-00152, "RS-232 transceiver with auto-power-down"
U18 U19 U20 U21 U24 U45: library part MCD-00136, "Dual Transil array for ESD protection"
U22: library part MCD-01160, "RS-485/RS-422 transceiver Up to 12Mbps"
U23 U26 U28: library part MCD-00264, "Dual bit dual supply bus transceiver"
U25: library part MCD-00159, "500mA, Enhanced single channel power switches with active high enable pin"
U27: library part MCD-00086, "Ultra low drop-low noise BiCMOS voltage, regulators low ESR capacitors compatible"
U29: library part MCD-00078, "Ultra low drop-low noise BiCMOS voltage, regulators low ESR capacitors compatible"
U30: library part MCD-00255, "Dual Transil array ESD protection"
U31: library part MCD-00649, "Common mode filter with ESD protection for USB 2.0 interface"
U32: library part MCD-00135, "Ultra-low-power 32-bit MCU ARM"
U33: library part MCD-01231, "3000 W Transil"
U34: library part MCD-00251, "High power transient voltage suppressor, 7V breakdown"
U35: library part MCD-00079, "Multi-Channel Audio Hub CODEC for Smartphones"
U36: library part MCD-01026, "High power transient voltage suppressor"
U37: library part MCD-01237, "4A step-down switching regulator"
U38 U39: library part MCD-00325, "Very high accuracy (5 ¦ÌV) zero drift micropower 5 V operational amplifiers"
U40: library part MCD-00596, "STM32F723IEK ?(STM32F7) BGA176"
U41: library part MCD-00247, "Quad Bidir ESD protection"
U42: library part MCD-01162, "Smartcard interfaces"
U43: library part MCD-01238, "3000 W Transil"
U46: library part MCD-00667, "4-line ESD protection for high speed lines"
U47: library part MCD-01025, "LDO, 3.3V, 1.3A, Very low quiescent current BiCMOS voltage regulator"
U48: library part MCD-00581, "LDO Linear Voltage Regulator IC Positive Adjustable 1 Output Adjustable 1.3A 6-DFN (3x3)"
U49: library part MCD-01066, "5 unidirectional Transil diodes ESD protection"
U53: library part MCD-01157, "Programmable voltage reference"
X1: library part MCD-00597, "Oscillator 25.00Mhz, -+50PPM, 3.3V, Temp -55 to +125¡ãC"
X2: library part MCD-01036, "24MHz crystal oscillator - Cl:6pf -"
X3: library part MCD-00091, "Crystal 32.768kHz, 6pF, -+20PPM, R=50K, SMD"

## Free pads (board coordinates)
  round 1.016 smd mask+1.016: 1(8.458,11.659) 1(13.36,158.471) 1(106.401,161.087)
  round 1.016 smd far side mask+1.016: 1(13.36,158.471) 1(102.616,9.322) 1(106.401,161.087)

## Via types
v1: diameter 0.508, hole 0.254, Top Layer to Bottom Layer, tented both sides, 1330 vias
v2: diameter 0.406, hole 0.203, Top Layer to Bottom Layer, tented both sides, 115 vias
v3: diameter 0.508, hole 0.254, Top Layer to Bottom Layer, 33 vias
v4: diameter 0.305, hole 0.152, Top Layer to Bottom Layer, tented both sides, 26 vias
v5: diameter 0.61, hole 0.305, Top Layer to Bottom Layer, tented both sides, 14 vias
v6: diameter 0.61, hole 0.33, Top Layer to Bottom Layer, tented both sides, 2 vias
v7: diameter 0.381, hole 0.203, Top Layer to Bottom Layer, tented both sides, 2 vias
v8: diameter 0.508, hole 0.203, Top Layer to Bottom Layer, tented both sides, 1 vias

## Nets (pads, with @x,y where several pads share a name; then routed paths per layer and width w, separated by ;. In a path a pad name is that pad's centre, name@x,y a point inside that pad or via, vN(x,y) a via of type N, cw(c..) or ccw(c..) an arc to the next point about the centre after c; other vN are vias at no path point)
1V8: C93.1 C97.2 C100.1 SB42.2 TP4.1 U35.D1 U35.D8 U35.G9 | length 24.4
  Top Layer w0.229: 85.9,45.463 85.903,45.466 ; U35.D8@89.577,45.466 v4(89.736,45.306) ; U35.G9@90.077,43.966 90.477,43.965
  Top Layer w0.249: 85.903,45.466 U35.D1@86.077,45.466
  Top Layer w0.254: C97.2@84.237,44.879 84.279,44.922 84.521,45.161 85.55,45.161 85.649,45.26 85.697,45.26 85.9,45.463 ; 90.477,43.965 91.343,43.101 C100.1@91.851,43.101
  Top Layer w0.508: TP4.1@77.948,68.278 77.948,62.027 81.506,58.468 81.506,53.642 82.522,52.626 ; C97.2@84.237,44.879 84.491,44.625 v1(85.062,44.625) ; v1(91.158,46.276) C93.1@91.978,46.276 ; v1(91.851,42.466) C100.1@91.851,43.101
  other v1: 82.776,50.721 83.538,50.721 82.776,51.483 83.538,51.483
1V8_LDO: C79.2 SB42.1 U29.5 | length 3.1
  Top Layer w0.508: C79.2@84.654,53.911 C79.2@84.653,53.912 ; 84.679,54.686 84.679,54.657 84.654,54.632 C79.2@84.654,53.911 85.138,53.911 ; 85.435,53.558 U29.5@86.264,53.559 ; 86.263,53.081 U29.5@86.264,53.559 ; 86.263,54.036 U29.5@86.264,53.559
3V3: C58.1 C62.2 C65.2 C70.2 C73.2 C84.2 C96.1 C186.1 CN2.28 CN4.28 CN24.1 CN24.2 CN28.4 JP6.3 JP11.1 LD1.1 LD2.1 LD3.1 LD4.1 R9.2 R23.2 R111.2 R191.1 R219.2 R226.1 R287.2 SB45.1 SB47.2 SW2.1 SW2.4 SW2.7 SW3.1 SW3.4 SW3.7 TP9.1 U17.22 U17.26 U22.8 U23.8 U26.8 U28.8 U29.1 U29.3 U35.B2 U35.C2 U35.E9 | length 38.5
  Top Layer w0.229: U35.C2@86.577,45.966 v4(86.416,46.124) U35.B2@86.577,46.466 ; U28.8@89.152,58.616 C70.2@90.307,58.616 ; U35.E9@90.077,44.966 90.396,44.966 90.899,45.469 C96.1@91.951,45.469
  Top Layer w0.254: U23.8@25.551,68.372 25.563,68.36 C62.2@25.563,67.182 ; U26.8@89.151,61.735 89.931,61.735 C65.2@90.331,61.337 ; C70.2@90.307,58.616 C70.2@90.331,58.594
  Top Layer w0.381: v1(23.434,87.711) U17.26@25.04,87.713 ; U17.22@25.04,85.113 26.888,85.113 C58.1@26.924,85.148 v1(27.777,85.146)
  Top Layer w0.508: R23.2@11.118,149.606 11.118,149.603 v1(11.986,149.603) ; v1(17.366,70.665) U22.8@17.367,72.141 ; R191.1@19.847,78.409 v1(19.848,79.233) ; C62.2@25.563,67.182 v1(26.591,67.18) ; v1(25.88,4.016) LD1.1@26.924,4.016 ; v1(28.166,4.016) LD2.1@29.143,4.016 ; v1(30.579,4) LD3.1@31.567,4.002 ; v1(32.865,4) LD4.1@33.81,4.002 ; 37.521,14.526 TP9.1@38.199,14.526 ; 38.199,13.848 TP9.1@38.199,14.526 ; 38.199,15.204 TP9.1@38.199,14.526 ; 38.877,14.526 TP9.1@38.199,14.526 ; v1(84.778,49.675) C84.2@85.529,48.926 ; C84.2@85.529,48.926 C84.2@85.529,48.925 ; U29.1@88.464,53.559 v1(89.616,53.558) ; U29.3@88.464,55.459 90.315,55.458 90.411,55.557 v1(91.412,55.557) ; v1(88.872,31.036) 88.872,30.183 SB45.1@89.035,30.023 ; C70.2@90.331,58.594 v1(90.33,59.55) ; C65.2@90.331,61.337 v1(90.33,62.238) ; R9.2@91.945,157.665 v1(93.182,157.663) ; C96.1@91.951,45.469 91.951,45.23 v1(92.428,44.752) ; R287.2@93.323,19.176 v1(93.322,20.119) ; v1(93.546,59.637) 94.31,59.637 R219.2@94.311,59.639 ; v1(93.848,53.619) R226.1@94.673,53.619 ; v1(95.522,14.318) CN28.4@95.523,15.625 ; v1(110.335,122.73) 110.335,122.349 110.876,121.808 R111.2@111.15,121.808
  Bottom Layer w0.508: v1(95.522,14.318) 95.915,14.712 C186.1@95.915,15.415
  other v1: 93.825,12.748 94.46,12.748 95.095,12.748 37.183,13.256 37.818,13.256 38.453,13.256 93.825,13.51 94.46,13.51 95.095,13.51 37.183,14.018 37.183,14.907
3V3_STLK: C67.2 C68.2 C113.2 C116.2 C117.2 C118.2 C128.2 C130.2 C131.2 C133.2 C134.2 C135.2 C136.2 C137.2 C138.2 C139.2 C140.2 C142.2 C143.2 C144.2 C145.2 C148.2 CN27.1 LD8.4 R278.1 R288.1 U27.5 U40.C1 U40.C5 U40.C7 U40.C8 U40.C9 U40.F3 U40.G3 U40.G13 U40.H13 U40.J12 U40.J13 U40.K4 U40.N8 U40.N9 U40.N10 U40.P1 U40.R1 X1.4 | length 78.3
  Top Layer w0.254: v1(75.537,24.559) 75.537,24.064 75.702,23.899 76.205,24.399 U40.C1@76.205,25.653 ; v2(75.901,29.249) U40.C7@76.203,29.551 ; v2(75.901,30.505) U40.C8@76.203,30.203 ; v2(75.901,31.155) U40.C9@76.203,30.853 ; v2(75.902,27.949) U40.C5@76.205,28.251 ; v2(77.852,26.65) U40.F3@78.155,26.953 ; v2(78.501,33.755) U40.G13@78.805,33.453 ; v2(78.502,26.65) U40.G3@78.805,26.953 ; U40.H13@79.455,33.453 v2(79.757,33.756) ; U40.J12@80.105,32.803 v2(80.407,33.106) ; U40.J13@80.105,33.453 v2(80.407,33.756) ; U40.K4@80.755,27.603 v2(81.057,27.3) ; U40.N8@82.705,30.203 v2(83.007,30.505) ; U40.N9@82.705,30.853 v2(83.007,31.155) ; U40.N10@82.705,31.503 v2(83.007,31.805) ; v1(83.284,24.559) 83.274,24.549 83.274,24.188 83.563,23.899 83.576,23.899 83.792,24.112 83.792,25.215 83.657,25.347 83.657,25.35 U40.P1@83.355,25.653 ; U40.R1@84.005,25.653 84.308,25.35 84.308,24.13 C143.2@84.539,23.899 ; C143.2@84.541,23.899 C143.2@84.539,23.899 ; v1(84.935,24.686) 84.935,24.305 84.539,23.912 C143.2@84.539,23.899 ; C144.2@85.471,23.899 85.951,24.379 v1(85.951,24.559)
  Top Layer w0.508: v1(38.755,3.223) LD8.4@38.756,4.55 ; v1(71.092,27.887) R278.1@71.951,27.888 ; v1(71.377,24.402) C135.2@72.233,24.403 ; C133.2@72.843,28.912 v1(73.472,28.91) ; C134.2@72.851,25.798 v1(73.599,25.796) ; C131.2@72.851,29.799 v1(73.475,29.797) ; C136.2@73.417,23.968 v1(73.416,24.597) ; v1(74.521,18.959) R288.1@75.292,18.961 ; v1(76.18,21.13) C148.2@76.18,20.31 76.258,20.231 X1.4@77.338,20.231 ; C139.2@76.756,23.899 v1(76.756,24.559) ; v1(77.346,36.147) C116.2@77.347,36.969 ; C140.2@77.645,23.899 v1(77.645,24.559) ; v1(78.496,36.154) C117.2@78.497,36.969 ; C137.2@80.538,23.899 v1(80.538,24.559) ; v1(82.306,36.281) C118.2@82.307,36.969 ; v1(82.395,24.559) 82.606,24.348 C145.2@82.607,23.899 ; v1(83.782,35.872) C113.2@83.782,36.786 ; v1(85.204,30.925) C128.2@85.921,30.926 ; v1(85.212,29.916) C130.2@85.882,29.918
  Bottom Layer w0.508: v1(38.755,3.223) 39.136,2.842 66.317,2.842 70.206,6.731 70.206,14.643 v1(74.521,18.959)
  other v1: 55.979,56.436 56.614,56.436 57.376,56.436 57.503,57.071
5V: C44.1 C53.1 C150.1 C152.1 C153.2 C156.2 C159.2 CN2.25 CN4.25 CN5.60 CN6.60 JP12.2 JP12.4 JP12.6 JP12.8 JP12.10 Q4.3 R198.1 R241.2 R277.2 R289.2 R318.2 SB1.2 SB34.2 SB46.1 T8.4 U4.8 U10.3 U15.3 U42.6 U47.6 U48.6 | length 55.7
  Top Layer w0.508: v1(12.977,162.471) SB1.2@14.192,162.472 ; U48.6@33.116,16.924 34.63,16.921 C150.1@34.663,16.954 ; v1(34.516,112.443) 35.052,112.979 CN5.60@36.385,112.981 ; C150.1@34.663,16.956 C150.1@34.663,16.954 ; U15.3@35.761,95.759 37.264,95.758 C53.1@37.45,95.574 v1(38.433,95.573) ; U10.3@35.761,104.901 37.305,104.899 C44.1@37.45,104.756 v1(38.199,104.755) ; v1(35.771,16.954) C150.1@34.663,16.954 ; v1(38.555,105.439) SB34.2@39.723,105.439 ; 38.613,72.073 JP12.2@39.717,72.073 ; 39.164,75.441 R198.1@39.662,75.442 ; 39.662,74.762 R198.1@39.662,75.442 ; 39.662,76.119 R198.1@39.662,75.442 ; 39.715,73.175 JP12.2@39.717,72.073 ; 40.82,72.073 JP12.2@39.717,72.073 ; 41.153,72.073 JP12.4@42.257,72.073 ; 41.831,15.852 C156.2@42.456,15.852 ; 41.841,16.548 U47.6@41.842,16.977 42.245,16.975 ; 42.255,73.175 JP12.4@42.257,72.073 ; 42.456,16.35 C156.2@42.456,15.852 ; 42.944,17.602 R289.2@43.472,17.602 ; 43.078,15.852 C156.2@42.456,15.852 ; 43.36,72.073 JP12.4@42.257,72.073 ; 43.472,17.168 R289.2@43.472,17.602 ; 43.693,72.073 JP12.6@44.797,72.073 ; 44,17.602 R289.2@43.472,17.602 ; 44.795,73.175 JP12.6@44.797,72.073 ; 45.9,72.073 JP12.6@44.797,72.073 ; 46.233,72.073 JP12.8@47.337,72.073 ; 47.335,73.175 JP12.8@47.337,72.073 ; 48.44,72.073 JP12.8@47.337,72.073 ; 48.773,72.073 JP12.10@49.877,72.073 ; 49.875,73.175 JP12.10@49.877,72.073 ; 50.98,72.073 JP12.10@49.877,72.073 ; v1(52.042,14.272) 52.042,15.596 C152.1@52.695,16.25 53.185,15.758 v1(53.185,14.272) ; U42.6@54.393,19.585 54.394,19.583 54.394,18.651 54.709,18.336 54.709,17.259 54.963,17.005 55.471,17.513 v1(55.471,17.894) ; T8.4@58.951,47.708 59.225,47.437 R241.2@60.456,47.437 v1(60.455,48.511) ; R277.2@86.821,28.851 v1(87.574,28.849) ; v1(88.872,27.48) 88.872,28.311 SB46.1@89.035,28.473 ; CN6.60@104.965,112.981 108.123,112.979 v1(108.125,112.977) ; v1(109.7,146.67) 109.827,146.797 U4.8@110.985,146.797
  Bottom Layer w0.508: v1(109.7,146.67) 109.771,146.741 C159.2@110.931,146.741 ; v1(113.383,116.507) Q4.3@113.383,117.734 ; R318.2@116.304,118.219 116.304,117.523 v1(116.558,117.269)
  other v1: 43.533,15.923 44.295,15.923 43.533,16.558 44.295,16.558 44.295,17.193 33.881,98.473 35.405,98.6 33.881,99.235 35.405,99.362 33.881,100.124 35.405,100.124 1.75,101.648 2.512,101.648 3.274,101.648 1.75,102.41 2.512,102.41 3.274,102.41
5V_D: CN5.49 CN6.49 D4.1 JP12.5 | length 200
  Top Layer w0.508: v1(20.038,106.982) 24.229,106.982 25.753,108.506 25.753,112.062 29.182,115.491 29.182,118.666 29.845,119.329 CN5.49@31.285,119.331 ; D4.1@44.041,62.885 44.041,68.776 JP12.5@44.797,69.533 ; v1(96.683,110.094) 96.683,118.095 97.917,119.329 CN6.49@99.865,119.331
  L4_SIG w0.508: v1(20.038,106.982) 16.609,106.982 15.466,105.839 15.466,100.886 16.99,99.362 16.99,74.343 15.847,73.2 15.847,69.009 18.387,66.469 26.007,66.469 27.404,65.072 40.338,65.072 JP12.5@44.797,69.533
  Bottom Layer w0.508: JP12.5@44.797,69.533 46.589,67.739 51.28,67.739 51.788,68.247 51.788,77.086 58.316,83.614 80.973,83.614 86.51,89.151 93.317,89.151 95.222,91.056 95.222,108.633 v1(96.683,110.094)
5V_EXT: C95.2 C102.2 C109.1 D3.1 D9.1 JP12.7 L5.2 Q3.5 Q3.6 Q3.7 Q3.8 R247.2 TP5.1 U33.1 | length 14.5
  Top Layer w0.508: 19.708,48.054 Q3.8@20.308,48.054 20.308,48.763 ; Q3.7@20.983,48.054 20.983,48.788 ; Q3.6@21.633,48.054 21.633,48.828 ; 22.308,48.623 Q3.5@22.308,48.054 23.076,48.054 23.079,48.057 ; 23.837,46.038 C95.2@24.614,46.038 ; R247.2@24.614,44.815 C95.2@24.614,46.038 ; 24.614,47.092 C95.2@24.614,46.038 ; D3.1@45.8,62.894 TP5.1@45.799,65.786 45.799,67.996 JP12.7@47.337,69.533
  other v1: 29.591,53.238 30.353,53.238 29.639,54.021 30.353,54.034
5V_STLK: JP12.1 SB41.2 | length 27.6
  Top Layer w0.508: v1(58.392,56.507) 58.401,56.516 SB41.2@59.306,56.516
  Bottom Layer w0.508: JP12.1@39.717,69.533 45.573,63.675 55.725,63.675 58.392,61.008 v1(58.392,56.507)
5V_USB_CHGR: C81.1 C89.2 CN21.1 D6.1 JP12.9 R215.1 R221.1 U25.5 U34.1 | length 89.3
  Top Layer w0.381: 112.494,51.102 112.812,51.42 CN21.1@113.938,51.421
  Top Layer w0.508: 47.145,62.809 D6.1@47.594,62.81 ; 48.042,62.809 D6.1@47.594,62.81 ; JP12.9@49.877,69.533 47.595,67.249 D6.1@47.594,62.81 ; 61.119,63.294 63.853,63.294 64.869,62.278 64.869,59.103 64.028,58.262 R221.1@64.028,57.6 64.79,57.6 v1(64.806,57.584) ; 111.651,47.198 U34.1@111.652,47.778 ; 111.651,48.357 U34.1@111.652,47.778 ; 111.727,48.679 C89.2@111.727,49.302 ; 111.727,49.924 C89.2@111.727,49.302 ; 111.727,49.949 C81.1@111.727,50.572 ; 111.727,51.194 C81.1@111.727,50.572 ; 112.105,47.777 U34.1@111.652,47.778 ; 112.225,49.301 C89.2@111.727,49.302 ; 112.225,50.571 C81.1@111.727,50.572
  Bottom Layer w0.508: v1(64.806,57.584) 68.049,57.584 75.664,65.199 106.525,65.199 110.716,61.008 110.716,50.213 v1(112.494,48.435)
5V_USB_PD: D5.1 D8.2 D9.2 JP12.3 | length 7.4
  Top Layer w0.508: 41.77,62.878 D5.1@42.219,62.878 ; 41.882,63.881 41.882,69.157 JP12.3@42.257,69.533 ; 42.217,63.586 D5.1@42.219,62.878 ; 42.667,62.878 D5.1@42.219,62.878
